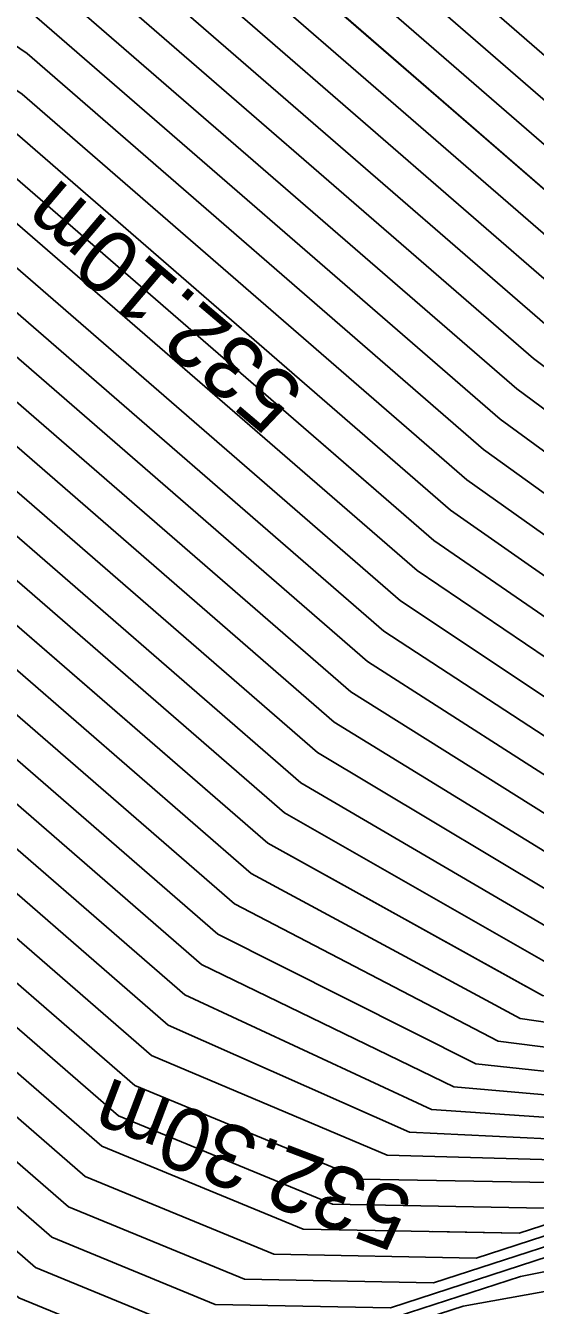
# Model space of a CAD drawing. Extents: x -866683 to -866410, y -1041951 to -1040252.
# Drawn here: x -866462.11 to -866459.69, y -1041913.86 to -1041907.77 of the extents above; entities that cross this region are included whole.
import ezdxf

# ---------------------------------------------------------------- set-up
doc = ezdxf.new("R2010")
doc.units = 0
for name, color, linetype in [('V-HL', 7, 'Continuous'), ('V-VEDL', 7, 'Continuous'), ('V_po_cm', 7, 'Continuous')]:
    doc.layers.add(name, color=color, linetype=linetype)

msp = doc.modelspace()

# ---------------------------------------------------------------- linework, layer by layer
at = {"layer": 'V-HL'}
msp.add_lwpolyline([(-866457.9912, -1041909.8721), (-866459.3844, -1041908.7805), (-866462.5795, -1041906.0104)], dxfattribs=at)
at = {"layer": 'V-VEDL'}
for points in [[(-866464.1795, -1041906.7476), (-866460.1736, -1041910.2204), (-866458.6026, -1041911.3017), (-866457.4635, -1041911.7277), (-866456.7563, -1041911.4985), (-866456.1765, -1041911.3679), (-866455.724, -1041911.3359), (-866455.0738, -1041911.4689)], [(-866456.0139, -1041911.9987), (-866456.2926, -1041911.9417), (-866456.7284, -1041912.0338), (-866457.4606, -1041912.2465), (-866458.4892, -1041912.5798), (-866459.6567, -1041912.3845), (-866460.9629, -1041911.6604), (-866463.8529, -1041909.155)], [(-866453.6171, -1041916.4043), (-866455.6514, -1041914.0403), (-866456.43, -1041913.2461), (-866456.9701, -1041912.8398), (-866457.2717, -1041912.8213), (-866457.8386, -1041912.9275), (-866458.6706, -1041913.1584), (-866459.7678, -1041913.5139), (-866460.795, -1041913.4946), (-866461.7521, -1041913.1004), (-866463.5263, -1041911.5623)]]:
    msp.add_lwpolyline(points, dxfattribs=at)
at = {"layer": 'V_po_cm'}
for points in [[(-866454.1839, -1041910.7122), (-866455.0956, -1041910.5257), (-866455.496, -1041910.4948), (-866455.8408, -1041910.5262), (-866456.1301, -1041910.6199), (-866457.2324, -1041909.894), (-866459.1476, -1041908.3485), (-866461.8758, -1041905.9832)], [(-866461.899, -1041906.1756), (-866459.2266, -1041908.4925), (-866457.3378, -1041910.0023), (-866456.2327, -1041910.7051), (-866455.9112, -1041910.601), (-866455.5281, -1041910.5661), (-866455.0833, -1041910.6004), (-866454.0702, -1041910.8077)], [(-866453.9556, -1041910.9838), (-866454.0116, -1041910.9187), (-866454.2068, -1041910.8609), (-866454.5691, -1041910.7779), (-866455.0986, -1041910.6695), (-866455.5694, -1041910.6355), (-866455.9817, -1041910.6758), (-866456.3353, -1041910.7903), (-866457.4432, -1041910.1106), (-866459.3055, -1041908.6365), (-866461.9221, -1041906.368)], [(-866461.9684, -1041906.7527), (-866459.4633, -1041908.9245), (-866457.654, -1041910.3271), (-866456.5404, -1041910.9608), (-866456.1225, -1041910.8254), (-866455.6798, -1041910.7687), (-866455.2123, -1041910.7907), (-866454.72, -1041910.8914), (-866454.3357, -1041911.0237), (-866454.0595, -1041911.1874), (-866453.7233, -1041911.5779)], [(-866453.0266, -1041913.3603), (-866454.2033, -1041911.9934), (-866454.7225, -1041911.5118), (-866455.1726, -1041911.2321), (-866455.5534, -1041911.1541), (-866456.0109, -1041911.1682), (-866456.5451, -1041911.2741), (-866457.1558, -1041911.4721), (-866458.2864, -1041910.9768), (-866459.9369, -1041909.7884), (-866462.1072, -1041907.9069), (-866463.5789, -1041906.9024)], [(-866453.6072, -1041911.875), (-866454.0835, -1041911.3217), (-866454.4002, -1041911.105), (-866454.7954, -1041910.9482), (-866455.2691, -1041910.8513), (-866455.735, -1041910.8352), (-866456.1929, -1041910.9002), (-866456.643, -1041911.046), (-866457.7594, -1041910.4354), (-866459.5423, -1041909.0685), (-866461.9915, -1041906.9451)], [(-866463.5642, -1041907.1206), (-866462.1303, -1041908.0993), (-866460.0158, -1041909.9324), (-866458.3918, -1041911.0851), (-866457.2584, -1041911.5573), (-866456.6155, -1041911.3489), (-866456.0661, -1041911.2347), (-866455.6103, -1041911.2147), (-866455.248, -1041911.2888), (-866454.787, -1041911.5932), (-866454.2273, -1041912.1278), (-866452.9104, -1041913.6573)], [(-866462.0146, -1041907.1374), (-866459.6212, -1041909.2125), (-866457.8648, -1041910.5437), (-866456.7455, -1041911.1312), (-866456.2634, -1041910.9749), (-866455.7902, -1041910.9018), (-866455.326, -1041910.9118), (-866454.8708, -1041911.005), (-866454.4647, -1041911.1864), (-866454.1075, -1041911.4561), (-866453.4911, -1041912.172)], [(-866452.7943, -1041913.9544), (-866454.2513, -1041912.2621), (-866454.8515, -1041911.6746), (-866455.3234, -1041911.3456), (-866455.6671, -1041911.2753), (-866456.1213, -1041911.3013), (-866456.6859, -1041911.4237), (-866457.361, -1041911.6425), (-866458.4972, -1041911.1934), (-866460.0947, -1041910.0764), (-866462.1534, -1041908.2917), (-866463.5495, -1041907.3388)], [(-866462.0378, -1041907.3298), (-866459.7001, -1041909.3565), (-866457.9702, -1041910.652), (-866456.8481, -1041911.2164), (-866456.3338, -1041911.0497), (-866455.8454, -1041910.9684), (-866455.3829, -1041910.9724), (-866454.9463, -1041911.0617), (-866454.5291, -1041911.2677), (-866454.1314, -1041911.5904), (-866453.3749, -1041912.4691)], [(-866462.0609, -1041907.5222), (-866459.779, -1041909.5005), (-866458.0756, -1041910.7603), (-866456.9507, -1041911.3016), (-866456.4042, -1041911.1245), (-866455.9006, -1041911.035), (-866455.4397, -1041911.033), (-866455.0217, -1041911.1185), (-866454.5936, -1041911.3491), (-866454.1554, -1041911.7247), (-866453.2588, -1041912.7662)], [(-866457.5936, -1041910.1836), (-866459.3844, -1041908.7805), (-866460.802, -1041907.5515)], [(-866464.0149, -1041919.5667), (-866464.1225, -1041917.511), (-866464.2372, -1041915.5405), (-866464.3589, -1041913.6552), (-866464.4877, -1041911.8549), (-866464.5437, -1041910.5382), (-866464.5268, -1041909.705), (-866464.4371, -1041909.3554), (-866464.355, -1041908.8981), (-866464.2806, -1041908.3332), (-866464.2137, -1041907.6608), (-866463.5201, -1041907.7752), (-866462.1997, -1041908.6764), (-866460.2526, -1041910.3644), (-866458.708, -1041911.41), (-866457.5661, -1041911.8129), (-866456.8268, -1041911.5733), (-866456.2317, -1041911.4345), (-866455.7809, -1041911.3965), (-866455.4743, -1041911.4592), (-866454.9804, -1041911.8373), (-866454.2992, -1041912.5308), (-866452.5621, -1041914.5485)], [(-866453.1427, -1041913.0632), (-866454.1794, -1041911.8591), (-866454.6581, -1041911.4305), (-866455.0971, -1041911.1753), (-866455.4966, -1041911.0936), (-866455.9557, -1041911.1016), (-866456.4746, -1041911.1993), (-866457.0533, -1041911.3868), (-866458.181, -1041910.8685), (-866459.8579, -1041909.6444), (-866462.084, -1041907.7146)], [(-866463.994, -1041919.6179), (-866464.1029, -1041917.5376), (-866464.2169, -1041915.5731), (-866464.3358, -1041913.7246), (-866464.4598, -1041911.992), (-866464.5119, -1041910.718), (-866464.4922, -1041909.9025), (-866464.4006, -1041909.5456), (-866464.3179, -1041909.0899), (-866464.2441, -1041908.5354), (-866464.1791, -1041907.8823), (-866463.5054, -1041907.9934), (-866462.2228, -1041908.8688), (-866460.3315, -1041910.5084), (-866458.8134, -1041911.5182), (-866457.6687, -1041911.8981), (-866456.8972, -1041911.6481), (-866456.2869, -1041911.5011), (-866455.8377, -1041911.457), (-866455.5498, -1041911.516), (-866455.0449, -1041911.9186), (-866454.3232, -1041912.6651), (-866452.446, -1041914.8455)], [(-866463.9732, -1041919.6692), (-866464.0834, -1041917.5641), (-866464.1965, -1041915.6057), (-866464.3127, -1041913.794), (-866464.4318, -1041912.1292), (-866464.4801, -1041910.8978), (-866464.4575, -1041910.1), (-866464.364, -1041909.7358), (-866464.2807, -1041909.2817), (-866464.2076, -1041908.7376), (-866464.1445, -1041908.1037), (-866463.4907, -1041908.2115), (-866462.2459, -1041909.0611), (-866460.4104, -1041910.6524), (-866458.9188, -1041911.6265), (-866457.7712, -1041911.9833), (-866456.9676, -1041911.7229), (-866456.342, -1041911.5677), (-866455.8946, -1041911.5176), (-866455.6252, -1041911.5727), (-866455.1094, -1041912), (-866454.3471, -1041912.7994), (-866452.3298, -1041915.1426)], [(-866463.9523, -1041919.7205), (-866464.0638, -1041917.5906), (-866464.1762, -1041915.6382), (-866464.2896, -1041913.8635), (-866464.4038, -1041912.2663), (-866464.4483, -1041911.0776), (-866464.4228, -1041910.2975), (-866464.3275, -1041909.926), (-866464.2436, -1041909.4735), (-866464.1711, -1041908.9398), (-866464.11, -1041908.3252), (-866463.476, -1041908.4297), (-866462.2691, -1041909.2535), (-866460.4893, -1041910.7964), (-866459.0242, -1041911.7348), (-866457.8738, -1041912.0686), (-866457.038, -1041911.7977), (-866456.3972, -1041911.6343), (-866455.9514, -1041911.5782), (-866455.7006, -1041911.6295), (-866455.1738, -1041912.0814), (-866454.3711, -1041912.9338), (-866452.2137, -1041915.4397)], [(-866463.9314, -1041919.7718), (-866464.0442, -1041917.6171), (-866464.1559, -1041915.6708), (-866464.2665, -1041913.9329), (-866464.3759, -1041912.4034), (-866464.4164, -1041911.2574), (-866464.3881, -1041910.495), (-866464.291, -1041910.1162), (-866464.2065, -1041909.6652), (-866464.1346, -1041909.142), (-866464.0754, -1041908.5467), (-866463.4613, -1041908.6479), (-866462.2922, -1041909.4459), (-866460.5683, -1041910.9404), (-866459.1296, -1041911.8431), (-866457.9764, -1041912.1538), (-866457.1084, -1041911.8725), (-866456.4524, -1041911.7008), (-866456.0083, -1041911.6388), (-866455.7761, -1041911.6863), (-866455.2383, -1041912.1627), (-866454.3951, -1041913.0681), (-866452.0976, -1041915.7367)], [(-866451.9815, -1041916.0338), (-866454.4191, -1041913.2024), (-866455.3028, -1041912.2441), (-866455.8515, -1041911.7431), (-866456.0651, -1041911.6993), (-866456.5076, -1041911.7674), (-866457.1789, -1041911.9473), (-866458.0789, -1041912.239), (-866459.2351, -1041911.9514), (-866460.6472, -1041911.0844), (-866462.3153, -1041909.6382), (-866463.4466, -1041908.8661), (-866464.0408, -1041908.7681), (-866464.0981, -1041909.3442), (-866464.1693, -1041909.857), (-866464.2544, -1041910.3064), (-866464.3535, -1041910.6925), (-866464.3846, -1041911.4372), (-866464.3479, -1041912.5405), (-866464.2433, -1041914.0023), (-866464.1356, -1041915.7034), (-866464.0247, -1041917.6436), (-866463.9105, -1041919.8231)], [(-866463.8897, -1041919.8744), (-866464.0051, -1041917.6701), (-866464.1153, -1041915.7359), (-866464.2202, -1041914.0717), (-866464.32, -1041912.6776), (-866464.3528, -1041911.617), (-866464.3188, -1041910.89), (-866464.2179, -1041910.4967), (-866464.1322, -1041910.0488), (-866464.0616, -1041909.5464), (-866464.0062, -1041908.9896), (-866463.4319, -1041909.0843), (-866462.3385, -1041909.8306), (-866460.7261, -1041911.2284), (-866459.3405, -1041912.0596), (-866458.1815, -1041912.3242), (-866457.2493, -1041912.0221), (-866456.5628, -1041911.834), (-866456.122, -1041911.7599), (-866455.9269, -1041911.7998), (-866455.3673, -1041912.3255), (-866454.443, -1041913.3368), (-866451.8653, -1041916.3308)], [(-866463.8688, -1041919.9257), (-866463.9855, -1041917.6967), (-866464.0949, -1041915.7685), (-866464.1971, -1041914.1412), (-866464.292, -1041912.8147), (-866464.321, -1041911.7968), (-866464.2841, -1041911.0875), (-866464.1814, -1041910.6869), (-866464.095, -1041910.2406), (-866464.0251, -1041909.7486), (-866463.9717, -1041909.2111), (-866463.4172, -1041909.3025), (-866462.3616, -1041910.023), (-866460.805, -1041911.3724), (-866459.4459, -1041912.1679), (-866458.2841, -1041912.4094), (-866457.3197, -1041912.0969), (-866456.618, -1041911.9006), (-866456.1789, -1041911.8205), (-866456.0024, -1041911.8566), (-866455.4317, -1041912.4068), (-866454.467, -1041913.4711), (-866451.7492, -1041916.6279)], [(-866451.6331, -1041916.9249), (-866454.491, -1041913.6054), (-866455.4962, -1041912.4882), (-866456.0778, -1041911.9134), (-866456.2357, -1041911.8811), (-866456.6732, -1041911.9672), (-866457.3901, -1041912.1717), (-866458.3867, -1041912.4946), (-866459.5513, -1041912.2762), (-866460.884, -1041911.5164), (-866462.3847, -1041910.2153), (-866463.4024, -1041909.5207), (-866463.9371, -1041909.4325), (-866463.9886, -1041909.9508), (-866464.0579, -1041910.4324), (-866464.1448, -1041910.8771), (-866464.2495, -1041911.285), (-866464.2892, -1041911.9766), (-866464.264, -1041912.9518), (-866464.174, -1041914.2106), (-866464.0746, -1041915.8011), (-866463.9659, -1041917.7232), (-866463.8479, -1041919.9769)], [(-866460.7343, -1041909.7344), (-866460.1736, -1041910.2204), (-866458.6026, -1041911.3017), (-866457.4635, -1041911.7277), (-866457.1815, -1041911.6363)], [(-866463.8062, -1041920.0795), (-866463.9268, -1041917.7762), (-866464.034, -1041915.8662), (-866464.1278, -1041914.3495), (-866464.2081, -1041913.226), (-866464.2256, -1041912.3362), (-866464.1801, -1041911.68), (-866464.0717, -1041911.2575), (-866463.9836, -1041910.8159), (-866463.9156, -1041910.3552), (-866463.8679, -1041909.8755), (-866463.373, -1041909.9571), (-866462.431, -1041910.6001), (-866461.0418, -1041911.8044), (-866459.7621, -1041912.4928), (-866458.5918, -1041912.665), (-866457.531, -1041912.3213), (-866456.7835, -1041912.1004), (-866456.3494, -1041912.0022), (-866456.2287, -1041912.0269), (-866455.6252, -1041912.6509), (-866454.5389, -1041913.8741), (-866451.4009, -1041917.519)], [(-866463.7853, -1041920.1308), (-866463.9072, -1041917.8027), (-866464.0137, -1041915.8988), (-866464.1046, -1041914.4189), (-866464.1802, -1041913.3631), (-866464.1938, -1041912.516), (-866464.1455, -1041911.8775), (-866464.0352, -1041911.4477), (-866463.9464, -1041911.0077), (-866463.8791, -1041910.5574), (-866463.8334, -1041910.0969), (-866463.3583, -1041910.1753), (-866462.4541, -1041910.7924), (-866461.1207, -1041911.9484), (-866459.8675, -1041912.601), (-866458.6944, -1041912.7503), (-866457.6014, -1041912.3961), (-866456.8387, -1041912.1669), (-866456.4063, -1041912.0628), (-866456.3041, -1041912.0837), (-866455.6896, -1041912.7323), (-866454.5629, -1041914.0085), (-866451.2847, -1041917.8161)], [(-866462.6617, -1041910.2344), (-866462.4079, -1041910.4077), (-866460.9629, -1041911.6604), (-866459.7349, -1041912.3411)], [(-866463.7645, -1041920.1821), (-866463.8876, -1041917.8293), (-866463.9933, -1041915.9313), (-866464.0815, -1041914.4883), (-866464.1522, -1041913.5002), (-866464.162, -1041912.6958), (-866464.1108, -1041912.075), (-866463.9987, -1041911.638), (-866463.9093, -1041911.1995), (-866463.8427, -1041910.7596), (-866463.7988, -1041910.3184), (-866463.3436, -1041910.3934), (-866462.4773, -1041910.9848), (-866461.1996, -1041912.0924), (-866459.9729, -1041912.7093), (-866458.7969, -1041912.8355), (-866457.6718, -1041912.4709), (-866456.8939, -1041912.2335), (-866456.4631, -1041912.1234), (-866456.3795, -1041912.1405), (-866455.7541, -1041912.8136), (-866454.5868, -1041914.1428), (-866451.1686, -1041918.1132)], [(-866451.0525, -1041918.4102), (-866454.6108, -1041914.2771), (-866455.8186, -1041912.895), (-866456.455, -1041912.1973), (-866456.52, -1041912.184), (-866456.9491, -1041912.3001), (-866457.7423, -1041912.5457), (-866458.8995, -1041912.9207), (-866460.0783, -1041912.8176), (-866461.2786, -1041912.2364), (-866462.5004, -1041911.1772), (-866463.3289, -1041910.6116), (-866463.7642, -1041910.5399), (-866463.8062, -1041910.9618), (-866463.8721, -1041911.3913), (-866463.9621, -1041911.8282), (-866464.0761, -1041912.2725), (-866464.1302, -1041912.8756), (-866464.1243, -1041913.6373), (-866464.0584, -1041914.5578), (-866463.973, -1041915.9639), (-866463.8681, -1041917.8558), (-866463.7436, -1041920.2334)], [(-866463.7227, -1041920.2847), (-866463.8485, -1041917.8823), (-866463.9527, -1041915.9965), (-866464.0353, -1041914.6272), (-866464.0963, -1041913.7744), (-866464.0983, -1041913.0554), (-866464.0414, -1041912.47), (-866463.9256, -1041912.0184), (-866463.835, -1041911.5831), (-866463.7697, -1041911.164), (-866463.7296, -1041910.7613), (-866463.3142, -1041910.8298), (-866462.5235, -1041911.3695), (-866461.3575, -1041912.3804), (-866460.1837, -1041912.9259), (-866459.0021, -1041913.0059), (-866457.8127, -1041912.6205), (-866457.0043, -1041912.3667), (-866456.5769, -1041912.2446), (-866456.5304, -1041912.2541), (-866455.883, -1041912.9764), (-866454.6348, -1041914.4115), (-866450.9364, -1041918.7073)], [(-866463.7019, -1041920.3359), (-866463.8289, -1041917.9088), (-866463.9324, -1041916.029), (-866464.0122, -1041914.6966), (-866464.0683, -1041913.9116), (-866464.0665, -1041913.2352), (-866464.0068, -1041912.6675), (-866463.889, -1041912.2086), (-866463.7978, -1041911.7748), (-866463.7332, -1041911.3662), (-866463.695, -1041910.9828), (-866463.2995, -1041911.048), (-866462.5467, -1041911.5619), (-866461.4364, -1041912.5244), (-866460.2891, -1041913.0342), (-866459.1046, -1041913.0911), (-866457.8831, -1041912.6953), (-866457.0595, -1041912.4333), (-866456.6337, -1041912.3051), (-866456.6058, -1041912.3108), (-866455.9475, -1041913.0577), (-866454.6587, -1041914.5458), (-866450.8202, -1041919.0043)], [(-866463.681, -1041920.3872), (-866463.8094, -1041917.9353), (-866463.912, -1041916.0616), (-866463.989, -1041914.766), (-866464.0404, -1041914.0487), (-866464.0347, -1041913.415), (-866463.9721, -1041912.865), (-866463.8525, -1041912.3988), (-866463.7607, -1041911.9666), (-866463.6967, -1041911.5684), (-866463.6605, -1041911.2043), (-866463.2848, -1041911.2662), (-866462.5698, -1041911.7543), (-866461.5153, -1041912.6684), (-866460.3945, -1041913.1424), (-866459.2072, -1041913.1763), (-866457.9535, -1041912.7701), (-866457.1147, -1041912.4999), (-866456.6906, -1041912.3657), (-866456.6813, -1041912.3676), (-866456.012, -1041913.1391), (-866454.6827, -1041914.6801), (-866450.7041, -1041919.3014)], [(-866459.3604, -1041913.2779), (-866460.5167, -1041913.2562), (-866461.5943, -1041912.8124), (-866462.5929, -1041911.9466), (-866463.2701, -1041911.4844), (-866463.6259, -1041911.4257), (-866463.6602, -1041911.7706), (-866463.7236, -1041912.1584), (-866463.816, -1041912.589), (-866463.9374, -1041913.0625), (-866464.0029, -1041913.5948), (-866464.0124, -1041914.1858), (-866463.9659, -1041914.8355), (-866463.8917, -1041916.0942), (-866463.7898, -1041917.9618), (-866463.6601, -1041920.4385)], [(-866463.6393, -1041920.4898), (-866463.7702, -1041917.9884), (-866463.8714, -1041916.1267), (-866463.9428, -1041914.9049), (-866463.9845, -1041914.3229), (-866463.9711, -1041913.7746), (-866463.9028, -1041913.2601), (-866463.7794, -1041912.7793), (-866463.6864, -1041912.3502), (-866463.6237, -1041911.9728), (-866463.5913, -1041911.6472), (-866463.2554, -1041911.7026), (-866462.6161, -1041912.139), (-866461.6732, -1041912.9564), (-866460.6559, -1041913.3754), (-866459.5641, -1041913.3959)], [(-866458.9433, -1041913.2987), (-866459.9715, -1041913.6319), (-866460.9341, -1041913.6138), (-866461.831, -1041913.2444), (-866462.6623, -1041912.5237), (-866463.226, -1041912.139), (-866463.5222, -1041912.0901), (-866463.5507, -1041912.3772), (-866463.6121, -1041912.7337), (-866463.7063, -1041913.1597), (-866463.8334, -1041913.6551), (-866463.9075, -1041914.1342), (-866463.9285, -1041914.5971), (-866463.8966, -1041915.0438), (-866463.8308, -1041916.1919), (-866463.7311, -1041918.0414), (-866463.5975, -1041920.5924)], [(-866463.5766, -1041920.6437), (-866463.7115, -1041918.0679), (-866463.8104, -1041916.2244), (-866463.8735, -1041915.1132), (-866463.9006, -1041914.7342), (-866463.8757, -1041914.314), (-866463.7987, -1041913.8526), (-866463.6698, -1041913.3499), (-866463.575, -1041912.9255), (-866463.5142, -1041912.5794), (-866463.4876, -1041912.3116), (-866463.2113, -1041912.3572), (-866462.6855, -1041912.7161), (-866461.91, -1041913.3884), (-866461.0732, -1041913.733), (-866460.1752, -1041913.7499), (-866459.216, -1041913.4391), (-866458.3956, -1041913.2429), (-866457.7139, -1041913.1615), (-866457.171, -1041913.1948), (-866456.1988, -1041913.9262), (-866454.7973, -1041915.3557), (-866452.9665, -1041917.4833), (-866451.6335, -1041919.0324)], [(-866450.0304, -1041921.0569), (-866454.4154, -1041915.9609), (-866456.0982, -1041914.2487), (-866457.2714, -1041913.3723), (-866457.935, -1041913.3316), (-866458.6741, -1041913.4007), (-866459.4888, -1041913.5794), (-866460.379, -1041913.8679), (-866461.2123, -1041913.8522), (-866461.9889, -1041913.5324), (-866462.7086, -1041912.9085), (-866463.1966, -1041912.5753), (-866463.453, -1041912.5331), (-866463.4777, -1041912.7816), (-866463.5378, -1041913.1173), (-866463.6333, -1041913.5401), (-866463.7641, -1041914.0501), (-866463.8439, -1041914.4938), (-866463.8726, -1041914.8713), (-866463.8503, -1041915.1826), (-866463.7901, -1041916.257), (-866463.6919, -1041918.0944), (-866463.5558, -1041920.6949)], [(-866463.6724, -1041918.121), (-866463.7698, -1041916.2896), (-866463.8272, -1041915.2521), (-866463.8447, -1041915.0084), (-866463.812, -1041914.6736), (-866463.7294, -1041914.2476), (-866463.5967, -1041913.7303), (-866463.5007, -1041913.3091), (-866463.4412, -1041912.9838), (-866463.4184, -1041912.7545), (-866463.1819, -1041912.7935), (-866462.7317, -1041913.1008), (-866462.0678, -1041913.6764), (-866461.3515, -1041913.9714), (-866460.5827, -1041913.9859), (-866459.7615, -1041913.7198), (-866458.9526, -1041913.5584), (-866458.1561, -1041913.5017), (-866457.3719, -1041913.5498), (-866456.1332, -1041914.4138), (-866454.4399, -1041916.0938), (-866450.1444, -1041921.0858)], [(-866460.1819, -1041913.5061), (-866459.7678, -1041913.5139), (-866458.6706, -1041913.1584), (-866457.8386, -1041912.9275), (-866457.2717, -1041912.8213), (-866456.9701, -1041912.8398), (-866456.43, -1041913.2461), (-866456.3058, -1041913.3727)], [(-866463.6528, -1041918.1475), (-866463.7495, -1041916.3221), (-866463.8041, -1041915.3215), (-866463.8167, -1041915.1455), (-866463.7802, -1041914.8534), (-866463.6947, -1041914.4451), (-866463.5602, -1041913.9206), (-866463.4635, -1041913.5009), (-866463.4048, -1041913.186), (-866463.3839, -1041912.976), (-866463.1672, -1041913.0117), (-866462.7549, -1041913.2932), (-866462.1467, -1041913.8204), (-866461.4906, -1041914.0906), (-866460.7864, -1041914.1039), (-866460.0342, -1041913.8601), (-866459.2312, -1041913.7161), (-866458.3772, -1041913.6718), (-866457.4723, -1041913.7273), (-866456.1681, -1041914.5789), (-866454.4645, -1041916.2267), (-866450.2585, -1041921.1147)]]:
    msp.add_lwpolyline(points, dxfattribs=at)

# ---------------------------------------------------------------- texts
for s, rotation, p in [('532.10m', 139.67921, (-866460.7752, -1041909.5029)), ('532.30m', 159.19105, (-866460.2576, -1041913.3253))]:
    msp.add_text(s, height=0.3, rotation=rotation, dxfattribs=at).set_placement(p)

doc.saveas('drawing.dxf')
